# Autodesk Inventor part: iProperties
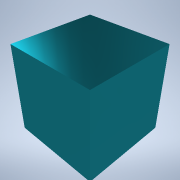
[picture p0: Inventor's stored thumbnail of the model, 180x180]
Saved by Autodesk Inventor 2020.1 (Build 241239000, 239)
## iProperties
Created: 2019-11
Part Number: iProperties
Material: Stainless Steel
Document SubType Name: Modeling
Designer: Synergysoft Dell02
Mass: 1000 g
Surface Area: 150 cm^2
Volume: 125 cm^3
Density: 8 g/cm^3
Appearance: Semi-Polished
Author: Synergysoft Dell02
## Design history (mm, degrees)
sketch "Sketch1"
  geometry: L1 (0, 0)-(50, 0); L2 (50, 0)-(50, 50); L3 (50, 50)-(0, 50); L4 (0, 50)-(0, 0)
  constraints: 8 end point, 2 parallel, 1 horizontal, 1 perpendicular
  dimensions: "d0" = 50 distance of L3.end L2.end; "d1" = 50 distance of L2.end L1.end
extrude "Extrusion1" new body sketch "Sketch1" distance "d2" = 50; taper "d3" = 0 deg
body "Solid1"
